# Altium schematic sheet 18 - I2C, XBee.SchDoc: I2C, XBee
size A3; PageSetup: Record=PageOptions¦CenterHorizontal=True¦CenterVertical=True¦PrintScale=0.70¦XCorrection=1.00¦YCorrection=1.00¦PrintKind=0¦BorderSize=5000000¦LeftOffset=0¦BottomOffset=0¦Orientation=2¦PaperLength=4200¦PaperWidth=2970¦Scale=100¦PaperSource=7¦PrintQuality=600¦MediaType=1¦DitherType=10¦PaperKind=A4¦PrintScaleMode=1; Author: Juan Anzola; SheetNumber: 18; SheetTotal: 21
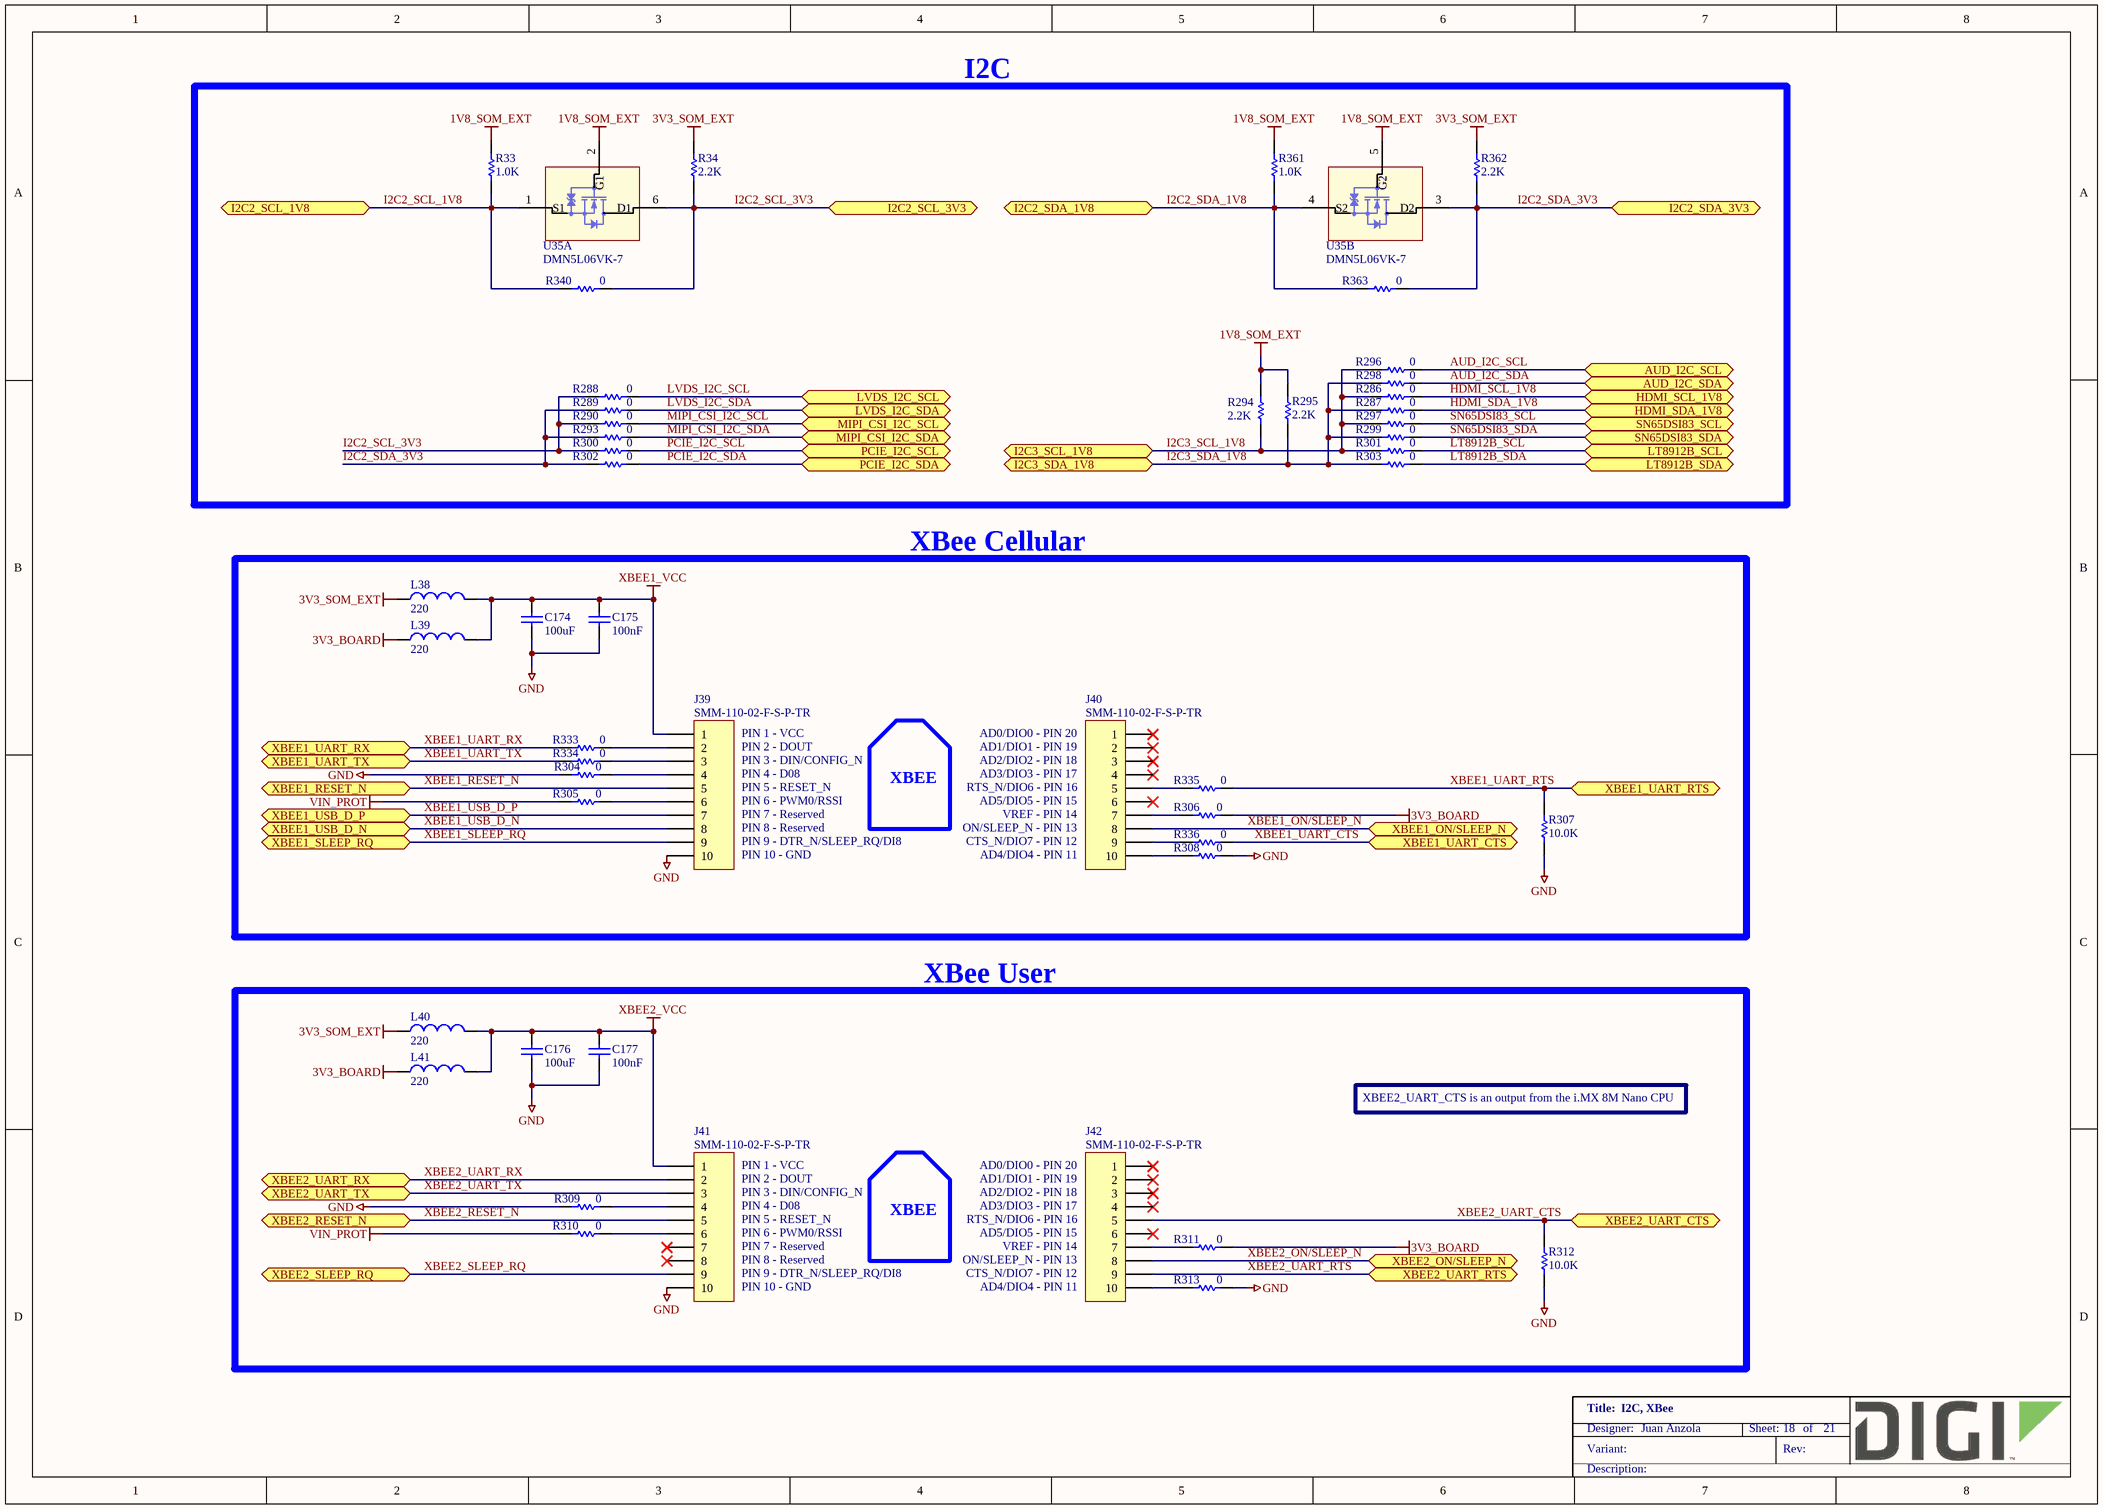
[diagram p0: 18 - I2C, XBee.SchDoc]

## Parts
C174  100uF  [CAPC3216X190N]
C175  100nF  [CAPC1005X55N]
C176  100uF  [CAPC3216X190N]
C177  100nF  [CAPC1005X55N]
J39  SMM-110-02-F-S-P-TR  [Samtec_SMM-110-02-F-S]
J40  SMM-110-02-F-S-P-TR  [Samtec_SMM-110-02-F-S]
J41  SMM-110-02-F-S-P-TR  [Samtec_SMM-110-02-F-S]
J42  SMM-110-02-F-S-P-TR  [Samtec_SMM-110-02-F-S]
L38  220  [INDC2013X110N]
L39  220  [INDC2013X110N]
L40  220  [INDC2013X110N]
L41  220  [INDC2013X110N]
R33  1.0K  [RESC1005X40N]
R34  2.2K  [RESC1005X40N]
R286  0  [RESC1005X40N]
R287  0  [RESC1005X40N]
R288  0  [RESC1005X40N]
R289  0  [RESC1005X40N]
R290  0  [RESC1005X40N]
R293  0  [RESC1005X40N]
R294  2.2K  [RESC1005X40N]
R295  2.2K  [RESC1005X40N]
R296  0  [RESC1005X40N]
R297  0  [RESC1005X40N]
R298  0  [RESC1005X40N]
R299  0  [RESC1005X40N]
R300  0  [RESC1005X40N]
R301  0  [RESC1005X40N]
R302  0  [RESC1005X40N]
R303  0  [RESC1005X40N]
R304  0  [RESC1005X40N]
R305  0  [RESC1005X40N]
R306  0  [RESC1005X40N]
R307  10.0K  [RESC1005X40N]
R308  0  [RESC1005X40N]
R309  0  [RESC1005X40N]
R310  0  [RESC1005X40N]
R311  0  [RESC1005X40N]
R312  10.0K  [RESC1005X40N]
R313  0  [RESC1005X40N]
R333  0  [RESC1005X40N]
R334  0  [RESC1005X40N]
R335  0  [RESC1005X40N]
R336  0  [RESC1005X40N]
R340  0  [RESC1005X40N]
R361  1.0K  [RESC1005X40N]
R362  2.2K  [RESC1005X40N]
R363  0  [RESC1005X40N]
U35  DMN5L06VK-7  [SOTFL50P160X60-6N]  (parts A,B of 2)

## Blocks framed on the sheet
I2C: R33 R34 R286-R290 R293-R303 R340 R361-R363 U35
XBee Cellular: C174 C175 J39 J40 L38 L39 R304-R308 R333-R336
XBee User: C176 C177 J41 J42 L40 L41 R309-R313

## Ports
AUD_I2C_SCL (bidir), AUD_I2C_SDA (bidir), HDMI_SCL_1V8 (bidir), HDMI_SDA_1V8 (bidir), I2C2_SCL_1V8 (bidir), I2C2_SCL_3V3 (bidir), I2C2_SDA_1V8 (bidir), I2C2_SDA_3V3 (bidir), I2C3_SCL_1V8 (bidir), I2C3_SDA_1V8 (bidir), LT8912B_SCL (bidir), LT8912B_SDA (bidir), LVDS_I2C_SCL (bidir), LVDS_I2C_SDA (bidir), MIPI_CSI_I2C_SCL (bidir), MIPI_CSI_I2C_SDA (bidir), PCIE_I2C_SCL (bidir), PCIE_I2C_SDA (bidir), SN65DSI83_SCL (bidir), SN65DSI83_SDA (bidir), XBEE1_ON/SLEEP_N (bidir), XBEE1_RESET_N (bidir), XBEE1_SLEEP_RQ (bidir), XBEE1_UART_CTS (bidir), XBEE1_UART_RTS (bidir), XBEE1_UART_RX (bidir), XBEE1_UART_TX (bidir), XBEE1_USB_D_N (bidir), XBEE1_USB_D_P (bidir), XBEE2_ON/SLEEP_N (bidir), XBEE2_RESET_N (bidir), XBEE2_SLEEP_RQ (bidir), XBEE2_UART_CTS (bidir), XBEE2_UART_RTS (bidir), XBEE2_UART_RX (bidir), XBEE2_UART_TX (bidir)

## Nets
1V8_SOM_EXT: R33.2 R294.2 R295.2 R361.2 U35.2(G1) U35.5(G2)
3V3_BOARD: L39.1 L41.1 R306.2 R311.2
3V3_SOM_EXT: L38.1 L40.1 R34.2 R362.2
GND: C174.1 C175.1 C176.1 C177.1 J39.10 J41.10 R304.1 R307.1 R308.2 R309.1 R312.1 R313.2
VIN_PROT: R305.1 R310.1
XBEE1_VCC: C174.2 C175.2 J39.1 L38.2 L39.2
XBEE2_VCC: C176.2 C177.2 J41.1 L40.2 L41.2
AUD_I2C_SCL: R296.2 ; port AUD_I2C_SCL
AUD_I2C_SDA: R298.2 ; port AUD_I2C_SDA
HDMI_SCL_1V8: R286.2 ; port HDMI_SCL_1V8
HDMI_SDA_1V8: R287.2 ; port HDMI_SDA_1V8
I2C2_SCL_1V8: R33.1 R340.1 U35.1(S1) ; port I2C2_SCL_1V8
I2C2_SCL_3V3: R34.1 R288.1 R290.1 R300.1 R340.2 U35.6(D1) ; port I2C2_SCL_3V3
I2C2_SDA_1V8: R361.1 R363.1 U35.4(S2) ; port I2C2_SDA_1V8
I2C2_SDA_3V3: R289.1 R293.1 R302.1 R362.1 R363.2 U35.3(D2) ; port I2C2_SDA_3V3
I2C3_SCL_1V8: R286.1 R294.1 R296.1 R297.1 R301.1 ; port I2C3_SCL_1V8
I2C3_SDA_1V8: R287.1 R295.1 R298.1 R299.1 R303.1 ; port I2C3_SDA_1V8
LT8912B_SCL: R301.2 ; port LT8912B_SCL
LT8912B_SDA: R303.2 ; port LT8912B_SDA
LVDS_I2C_SCL: R288.2 ; port LVDS_I2C_SCL
LVDS_I2C_SDA: R289.2 ; port LVDS_I2C_SDA
MIPI_CSI_I2C_SCL: R290.2 ; port MIPI_CSI_I2C_SCL
MIPI_CSI_I2C_SDA: R293.2 ; port MIPI_CSI_I2C_SDA
PCIE_I2C_SCL: R300.2 ; port PCIE_I2C_SCL
PCIE_I2C_SDA: R302.2 ; port PCIE_I2C_SDA
SN65DSI83_SCL: R297.2 ; port SN65DSI83_SCL
SN65DSI83_SDA: R299.2 ; port SN65DSI83_SDA
XBEE1_ON/SLEEP_N: J40.8 ; port XBEE1_ON/SLEEP_N
XBEE1_RESET_N: J39.5 ; port XBEE1_RESET_N
XBEE1_SLEEP_RQ: J39.9 ; port XBEE1_SLEEP_RQ
XBEE1_UART_CTS: R336.2 ; port XBEE1_UART_CTS
XBEE1_UART_RTS: R307.2 R335.2 ; port XBEE1_UART_RTS
XBEE1_UART_RX: R333.1 ; port XBEE1_UART_RX
XBEE1_UART_TX: R334.1 ; port XBEE1_UART_TX
XBEE1_USB_D_N: J39.8 ; port XBEE1_USB_D_N
XBEE1_USB_D_P: J39.7 ; port XBEE1_USB_D_P
XBEE2_ON/SLEEP_N: J42.8 ; port XBEE2_ON/SLEEP_N
XBEE2_RESET_N: J41.5 ; port XBEE2_RESET_N
XBEE2_SLEEP_RQ: J41.9 ; port XBEE2_SLEEP_RQ
XBEE2_UART_CTS: J42.5 R312.2 ; port XBEE2_UART_CTS
XBEE2_UART_RTS: J42.9 ; port XBEE2_UART_RTS
XBEE2_UART_RX: J41.2 ; port XBEE2_UART_RX
XBEE2_UART_TX: J41.3 ; port XBEE2_UART_TX
NetJ39_2: J39.2 R333.2
NetJ39_3: J39.3 R334.2
NetJ39_4: J39.4 R304.2
NetJ39_6: J39.6 R305.2
NetJ40_5: J40.5 R335.1
NetJ40_7: J40.7 R306.1
NetJ40_9: J40.9 R336.1
NetJ40_10: J40.10 R308.1
NetJ41_4: J41.4 R309.2
NetJ41_6: J41.6 R310.2
NetJ42_7: J42.7 R311.1
NetJ42_10: J42.10 R313.1

Not connected (* = marked no-connect by the designer): J40 1* 2* 3* 4* 6*; J41 7* 8*; J42 1* 2* 3* 4* 6*

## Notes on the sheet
- (near J39) PIN 1 - VCC
- (near J39) PIN 2 - DOUT
- (near J39) PIN 3 - DIN/CONFIG_N
- (near J39) PIN 4 - D08
- XBEE
- (near J40) AD0/DIO0 - PIN 20
- (near J40) AD1/DIO1 - PIN 19
- (near J40) AD2/DIO2 - PIN 18
- (near J40) AD3/DIO3 - PIN 17
- (near J39) PIN 5 - RESET_N
- (near J39) PIN 6 - PWM0/RSSI
- (near J39) PIN 7 - Reserved
- (near J39) PIN 8 - Reserved
- (near J39) PIN 9 - DTR_N/SLEEP_RQ/DI8
- (near J39) PIN 10 - GND
- (near J40) RTS_N/DIO6 - PIN 16
- (near J40) AD5/DIO5 - PIN 15
- (near J40) VREF - PIN 14
- (near J40) ON/SLEEP_N - PIN 13
- (near J40) CTS_N/DIO7 - PIN 12
- (near J40) AD4/DIO4 - PIN 11
- XBEE2_UART_CTS is an output from the i.MX 8M Nano CPU
- (near J41) PIN 1 - VCC
- (near J41) PIN 2 - DOUT
- (near J42) AD0/DIO0 - PIN 20
- (near J42) AD1/DIO1 - PIN 19
- (near J41) PIN 3 - DIN/CONFIG_N
- (near J41) PIN 4 - D08
- (near J41) PIN 5 - RESET_N
- (near J41) PIN 6 - PWM0/RSSI
- (near J41) PIN 7 - Reserved
- (near J41) PIN 8 - Reserved
- (near J42) AD2/DIO2 - PIN 18
- (near J42) AD3/DIO3 - PIN 17
- (near J42) RTS_N/DIO6 - PIN 16
- (near J42) AD5/DIO5 - PIN 15
- (near J42) VREF - PIN 14
- (near J42) ON/SLEEP_N - PIN 13
- (near J41) PIN 9 - DTR_N/SLEEP_RQ/DI8
- (near J41) PIN 10 - GND
- (near J42) CTS_N/DIO7 - PIN 12
- (near J42) AD4/DIO4 - PIN 11

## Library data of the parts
C174 C176 = 1000566: CAP CER 100UF 10V 20% X5R 1206; Part_Type: Capacitor; Manufacturer: TDK Corporation; Manufacturer_Part_Number: C3216X5R1A107M; Digi_PN: 14050666; Component_Life_Cycle_State: Reviewed; Area: 7.47; Project: GSM Cell PCB
C175 C177 = 1000006: CAP 100nF 16V 10% X7R 0402; Part_Type: Capacitor; Manufacturer: Murata; Manufacturer_Part_Number: GRM155R71C104KA88D; Component_Life_Cycle_State: CAD Reviewed; Area: 0.95; Project: KITT; Tolerance: 10; Digi_PN: 14050552
J39-J42 = 1001495: CONN RCPT 2MM 10POS SMD; Part_Type: Connector; Manufacturer: Samtec; Digi_PN: 19050036; Component_Life_Cycle_State: Reviewed; Area: 105; Project: CCWMX6_SBC board
L38-L41 = 1001174: FERRITE BEAD 220 OHM 2.0A 0805; Manufacturer: Wurth Electronics Inc; Manufacturer_Part_Number: 742792022; Digi_PN: 21000146; Component_Life_Cycle_State: Reviewed; Area: 4.24; Project: CCWMX6_SBC board
R33 R361 = 1000079: RES 1.00K OHM 1/10W 1% 0402 SMD; Part_Type: Resistor; Manufacturer: Panasonic - ECG; Manufacturer_Part_Number: ERJ-2RKF1001X; Digi_PN: 13051085; Component_Life_Cycle_State: Proven; Area: 0,95; Project: Adjustable Foundation; Power_WV_SRF: 10
R34 R362 = 1001156: RES 2.20K OHM 1/16W 1% 0402 SMD; Part_Type: Resistor; Manufacturer: Yageo; Manufacturer_Part_Number: RC0402FR-072K2L; Note: 13051099 = Digi No. for GE WDNU; Digi_PN: 13050699; Component_Life_Cycle_State: Reviewed; Area: 0,95
R286-R290 R293 R296-R306 R308-R311 R313 = 1000076: RES 0.0 OHM 1/10W 0402 SMD; Part_Type: Resistor; Manufacturer: Panasonic - ECG; Manufacturer_Part_Number: ERJ-2GE0R00X; Component_Life_Cycle_State: Proven; Area: 0.95; Project: Adjustable Foundation; Power_WV_SRF: 10; Digi_PN: 13050387
R294 R295 = 1001156: RES 2.20K OHM 1/16W 1% 0402 SMD; Part_Type: Resistor; Manufacturer: Yageo; Manufacturer_Part_Number: RC0402FR-072K2L; Digi_PN: 13050699; Component_Life_Cycle_State: Reviewed; Area: 0.95; Project: CCWMX6_SBC board; Note: 13051099 = Digi No. for GE WDNU
R307 R312 = 1000537: RES 10.0K OHM 1/10W 1% 0402 SMD; Part_Type: Resistor; Manufacturer: Panasonic - ECG; Manufacturer_Part_Number: ERJ-2RKF1002X; Component_Life_Cycle_State: CAD Reviewed; Area: 0.95; Project: KITT; Power_WV_SRF: 100; Digi_PN: 13051084
R333-R336 R340 R363 = 1000076: RES 0.0 OHM 1/10W 0402 SMD; Part_Type: Resistor; Manufacturer: Panasonic - ECG; Manufacturer_Part_Number: ERJ-2GE0R00X; Digi_PN: 13050387; Component_Life_Cycle_State: Proven; Area: 0,95; Power_WV_SRF: 10
U35 = 1002493: MOSFET 2N-CH 30V 0.1A ES6; Part_Type: Transistor; Manufacturer: Diodes, Inc.; Digi_PN: 17000134; Component_Life_Cycle_State: Reviewed; Area: 4,88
